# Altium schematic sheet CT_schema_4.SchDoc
size 207 x 169 mm
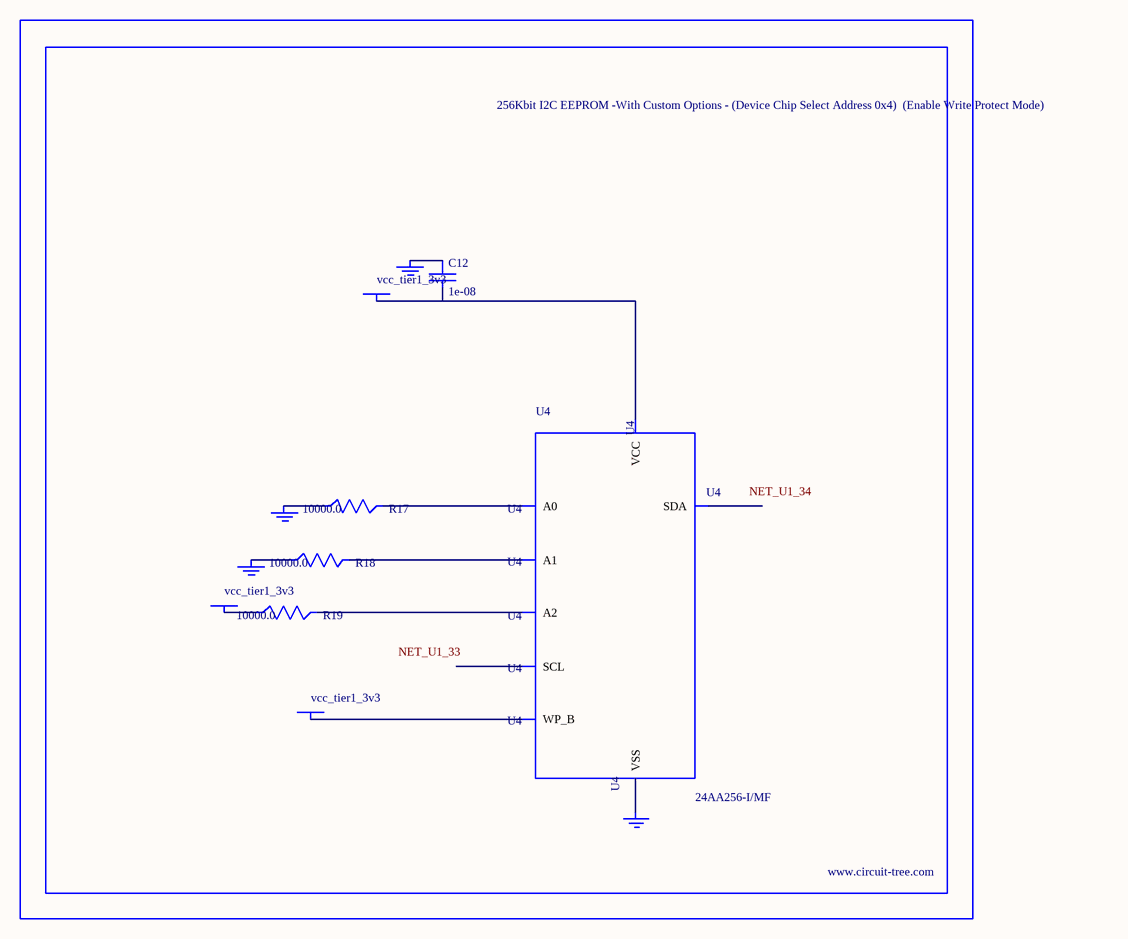
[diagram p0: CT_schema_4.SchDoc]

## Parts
BORDER3  (no value)
C12  1e-08  [C0402]
GND_INSTANCE_3_0  (no value)
GND_INSTANCE_3_1  (no value)
GND_INSTANCE_3_2  (no value)
GND_INSTANCE_3_3  (no value)
POWER_INSTANCE_3_0  vcc_tier1_3v3
POWER_INSTANCE_3_1  vcc_tier1_3v3
POWER_INSTANCE_3_2  vcc_tier1_3v3
R17  10000.0  [R0603]
R18  10000.0  [R0603]
R19  10000.0  [R0603]
U4  24AA256-I/MF  [DFN8-S]

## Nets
NetC12_1: C12.1 GND_INSTANCE_3_2.0(GND)
NetC12_2: C12.2 POWER_INSTANCE_3_2.0(PWR) U4.8(VCC)
NetGND_INSTANCE_3_0_0: GND_INSTANCE_3_0.0(GND) R17.1
NetGND_INSTANCE_3_1_0: GND_INSTANCE_3_1.0(GND) R18.1
NetGND_INSTANCE_3_3_0: GND_INSTANCE_3_3.0(GND) U4.4(VSS)
NetPOWER_INSTANCE_3_0_0: POWER_INSTANCE_3_0.0(PWR) R19.1
NetPOWER_INSTANCE_3_1_0: POWER_INSTANCE_3_1.0(PWR) U4.7(WP_B)
NetR17_2: R17.2 U4.1(A0)
NetR18_2: R18.2 U4.2(A1)
NetR19_2: R19.2 U4.3(A2)

Not connected (* = marked no-connect by the designer): U4 5(SDA) 6(SCL)

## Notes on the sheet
- Labels drawn without touching a wire or pin: NET_U1_33, NET_U1_34

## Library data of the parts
BORDER3 = BORDER_PAGE3
C12 = C0402C103K3RAC
GND_INSTANCE_3_0-GND_INSTANCE_3_3 = GND
POWER_INSTANCE_3_0-POWER_INSTANCE_3_2 = PWR
R17-R19 = RC0603JR-0710KL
